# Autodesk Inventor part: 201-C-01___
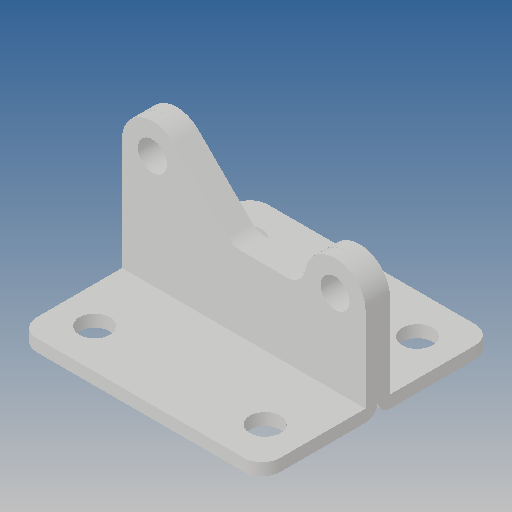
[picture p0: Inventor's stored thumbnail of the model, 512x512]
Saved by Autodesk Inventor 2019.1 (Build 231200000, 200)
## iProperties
Created: 2010-06
Part Number: 201-C-01___
Material: Ogólny
Document SubType Name: Modeling
Designer: CADENGINEERING4
Density: 1 g/cm^3
Appearance: Domyślna
Author: CADENGINEERING4
Revision Number: ANY
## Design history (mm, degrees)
feature "NONE"
feature "NONE:1"
node "Bryła1"
node "Bryła2"
